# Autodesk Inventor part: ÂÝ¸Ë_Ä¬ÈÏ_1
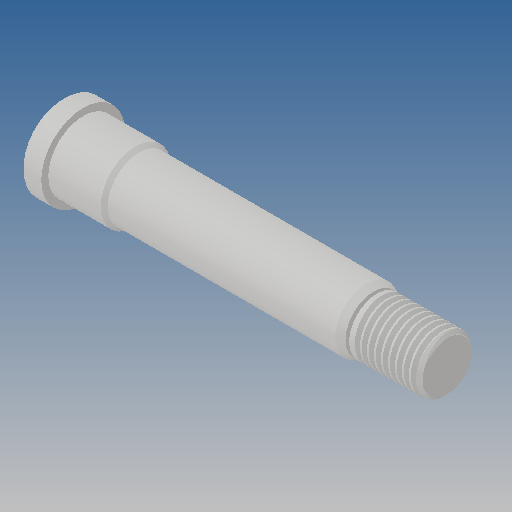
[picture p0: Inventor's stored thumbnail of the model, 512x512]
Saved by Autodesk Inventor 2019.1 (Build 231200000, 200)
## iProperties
Created: 2012-10
Part Number: ÂÝ¸Ë_Ä¬ÈÏ_1
Material: Ogólny
Document SubType Name: Modeling
Designer: CADENGINEERING4
Density: 1 g/cm^3
Appearance: Domyślna
Author: CADENGINEERING4
Revision Number: ÈÎºÎ
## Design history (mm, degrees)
feature "NONE"
node "Bryła1"
